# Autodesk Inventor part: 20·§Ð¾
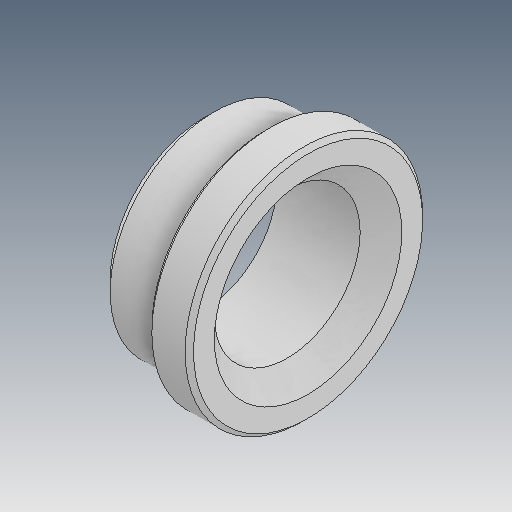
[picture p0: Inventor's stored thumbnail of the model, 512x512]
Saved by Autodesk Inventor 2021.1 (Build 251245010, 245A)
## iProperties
Created: 2019-12
Part Number: 20·§Ð¾
Material: Ogólny
Document SubType Name: Modeling
Designer: user
Density: 1 g/cm^3
Appearance: Domyślna
Author: user
Revision Number: ÈÎºÎ
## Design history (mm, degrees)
feature "ÊäÈë1"
node "Bryła1"
